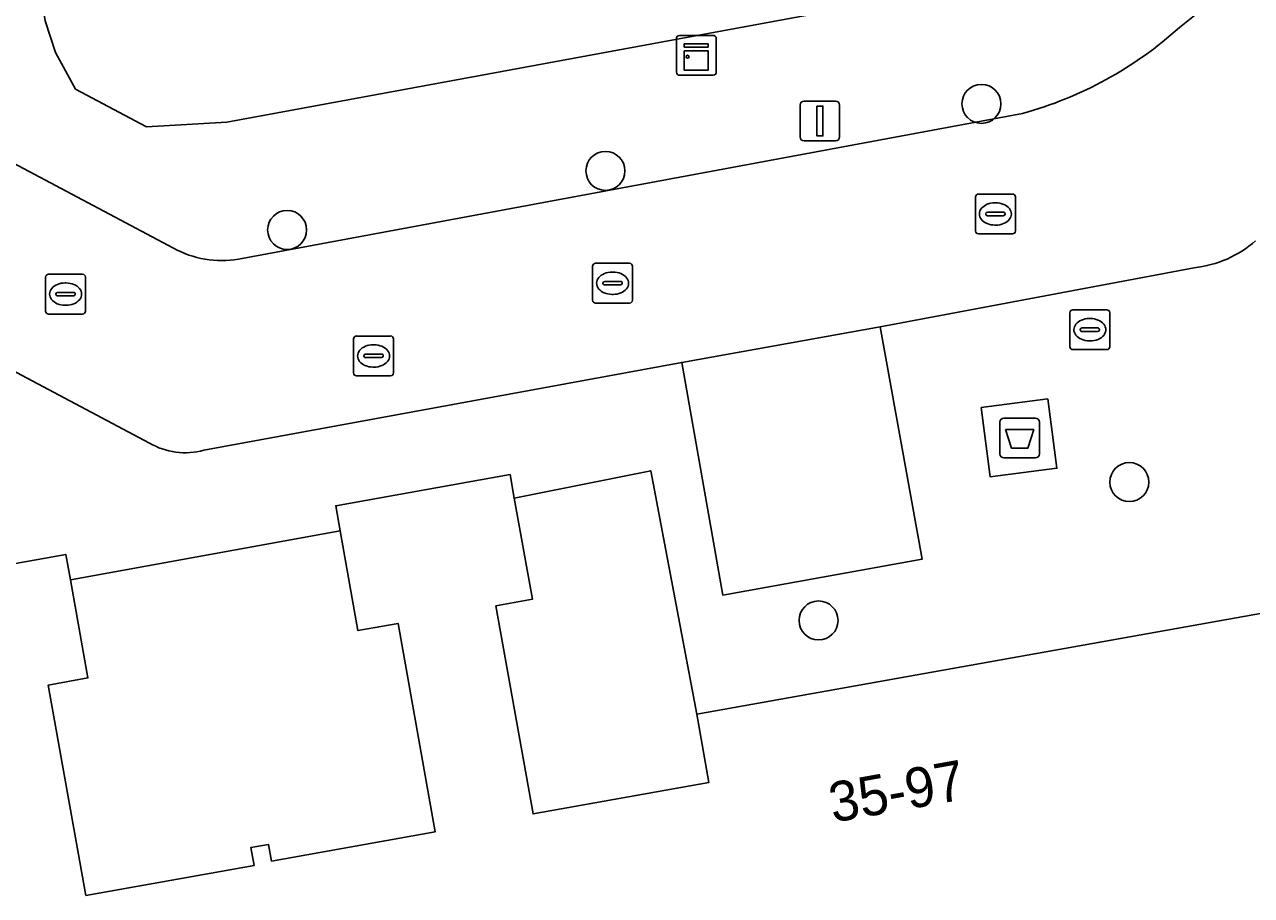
# Model space of a CAD drawing. Extents: x 157793 to 159380, y 380877 to 382313.
# Drawn here: x 158435.44 to 158466.23, y 381426.16 to 381448 of the extents above; entities that cross this region are included whole.
import ezdxf

# ---------------------------------------------------------------- set-up
doc = ezdxf.new("R2010")
doc.units = 0
for name, color, linetype in [('IMGEO_Afval_apart_plaats', 7, 'Continuous'), ('IMGEO_Boom', 7, 'Continuous'), ('IMGEO_Brandkraan', 7, 'Continuous'), ('IMGEO_Erf', 7, 'Continuous'), ('IMGEO_Kast', 7, 'Continuous'), ('IMGEO_Kolk', 7, 'Continuous'), ('IMGEO_Lichtmast', 7, 'Continuous'), ('IMGEO_Pand', 7, 'Continuous'), ('IMGEO_Pand_nummerreeks', 7, 'Continuous'), ('IMGEO_Parkeervlak_open', 7, 'Continuous'), ('IMGEO_Rijbaan_lokaal_open', 7, 'Continuous'), ('IMGEO_Rioolput', 7, 'Continuous'), ('IMGEO_Voetpad_gesloten', 7, 'Continuous'), ('IMGEO_Voetpad_open', 7, 'Continuous')]:
    doc.layers.add(name, color=color, linetype=linetype)

msp = doc.modelspace()

# ---------------------------------------------------------------- linework, layer by layer
at = {"layer": 'IMGEO_Afval_apart_plaats'}
for p, q in [((158459.916, 381437.227), (158459.916, 381438.027)), ((158459.916, 381438.027), (158459.916, 381437.227)), ((158460.016, 381438.127), (158460.806, 381438.127)), ((158460.806, 381438.127), (158460.016, 381438.127)), ((158460.906, 381438.027), (158460.906, 381437.227)), ((158460.906, 381437.227), (158460.906, 381438.027)), ((158460.806, 381437.127), (158460.016, 381437.127)), ((158460.016, 381437.127), (158460.806, 381437.127))]:
    msp.add_line(p, q, dxfattribs=at)
msp.add_lwpolyline([(158460.059, 381437.841), (158460.763, 381437.841), (158460.614, 381437.371), (158460.208, 381437.371), (158460.059, 381437.841)], dxfattribs=at)
for centre, start, end in [((158460.016, 381438.027), 90, 180), ((158460.016, 381438.027), 90, 180), ((158460.806, 381438.027), 0, 90), ((158460.806, 381438.027), 360, 90), ((158460.016, 381437.227), 180, 270), ((158460.016, 381437.227), 180, 270), ((158460.806, 381437.227), 270, 0), ((158460.806, 381437.227), 270, 0)]:
    msp.add_arc(centre, 0.1, start, end, dxfattribs=at)
at = {"layer": 'IMGEO_Boom'}
for centre in [(158459.452, 381446.008), (158450.018, 381444.327), (158442.032, 381442.847), (158463.162, 381436.522), (158455.365, 381433.052)]:
    msp.add_circle(centre, 0.489, dxfattribs=at)
at = {"layer": 'IMGEO_Brandkraan'}
for p, q in [((158461.746, 381440.844), (158462.598, 381440.844)), ((158461.671, 381439.918), (158461.671, 381440.77)), ((158462.159, 381440.624), (158462.184, 381440.624)), ((158462.672, 381440.77), (158462.672, 381439.918)), ((158461.93, 381440.338), (158461.93, 381440.35)), ((158462.368, 381440.301), (158461.97, 381440.301)), ((158461.973, 381440.387), (158462.371, 381440.387)), ((158462.414, 381440.35), (158462.414, 381440.338)), ((158462.182, 381440.064), (158462.157, 381440.064)), ((158462.598, 381439.844), (158461.746, 381439.844))]:
    msp.add_line(p, q, dxfattribs=at)
for points in [[(158461.746, 381440.844), (158462.598, 381440.844)], [(158461.671, 381439.918), (158461.671, 381440.77)], [(158462.672, 381440.77), (158462.672, 381439.918)], [(158462.598, 381439.844), (158461.746, 381439.844)]]:
    msp.add_lwpolyline(points, dxfattribs=at)
for centre, radius, start, end in [((158461.748, 381440.768), 0.0765, 91.552, 178.448), ((158461.748, 381440.768), 0.0765, 91.552, 178.448), ((158462.596, 381440.768), 0.0765, 1.552, 88.448), ((158462.596, 381440.768), 0.0765, 1.552, 88.448), ((158461.97, 381440.347), 0.0403, 85.8775, 175.7526), ((158461.967, 381440.337), 0.0366, 178.938, 274.7102), ((158462.371, 381440.344), 0.043, 264.8664, 352.4533), ((158462.375, 381440.349), 0.0386, 1.7309, 96.639), ((158461.748, 381439.92), 0.0765, 181.552, 268.448), ((158461.748, 381439.92), 0.0765, 181.552, 268.448), ((158462.596, 381439.92), 0.0765, 271.552, 358.448), ((158462.596, 381439.92), 0.0765, 271.552, 358.448)]:
    msp.add_arc(centre, radius, start, end, dxfattribs=at)
for centre, major_axis, ratio, start_param, end_param in [((158462.158, 381440.344), (-0.387, 0.002), 0.722429, 4.712389, 7.853982), ((158462.183, 381440.344), (-0.39, 0.002), 0.717154, 1.570796, 4.712389)]:
    msp.add_ellipse(centre, major_axis=major_axis, ratio=ratio, start_param=start_param, end_param=end_param, dxfattribs=at)
at = {"layer": 'IMGEO_Erf'}
msp.add_lwpolyline([(158435.964, 381448.094), (158436.22, 381447.293), (158436.724, 381446.379), (158438.502, 381445.428), (158440.515, 381445.553), (158459.22, 381448.998)], dxfattribs=at)
for points in [[(158451.154, 381436.805), (158447.73, 381436.121), (158448.184, 381433.582), (158447.27, 381433.418), (158448.203, 381428.2), (158452.616, 381428.989), (158452.31, 381430.699)], [(158436.593, 381434.067), (158437.032, 381431.609), (158436.04, 381431.431), (158436.983, 381426.155), (158441.204, 381426.91), (158441.124, 381427.358), (158441.564, 381427.437), (158441.639, 381427.019), (158445.75, 381427.754), (158444.816, 381432.978), (158443.809, 381432.798), (158443.362, 381435.3)]]:
    msp.add_lwpolyline(points, close=True, dxfattribs=at)
at = {"layer": 'IMGEO_Kast'}
for p, q in [((158451.8, 381446.801), (158451.8, 381447.642)), ((158451.8, 381447.642), (158451.8, 381446.801)), ((158451.875, 381447.726), (158452.716, 381447.726)), ((158452.716, 381447.726), (158451.875, 381447.726)), ((158452.8, 381447.651), (158452.8, 381446.81)), ((158452.8, 381446.81), (158452.8, 381447.651)), ((158452.725, 381446.726), (158451.884, 381446.726)), ((158451.884, 381446.726), (158452.725, 381446.726))]:
    msp.add_line(p, q, dxfattribs=at)
for points in [[(158451.995, 381447.516), (158452.595, 381447.516), (158452.595, 381447.431), (158451.995, 381447.431), (158451.995, 381447.516)], [(158451.995, 381447.341), (158452.595, 381447.341), (158452.595, 381446.852), (158451.995, 381446.852), (158451.995, 381447.341)]]:
    msp.add_lwpolyline(points, dxfattribs=at)
msp.add_circle((158452.079, 381447.19), 0.0377, dxfattribs=at)
for centre, start, end in [((158451.878, 381447.648), 92.4484, 184.2845), ((158451.878, 381447.648), 92.4484, 184.2845), ((158452.722, 381447.648), 2.4484, 94.2845), ((158452.722, 381447.648), 2.4484, 94.2845), ((158451.878, 381446.804), 182.4484, 274.2845), ((158451.878, 381446.804), 182.4484, 274.2845), ((158452.722, 381446.804), 272.4484, 4.2845), ((158452.722, 381446.804), 272.4484, 4.2845)]:
    msp.add_arc(centre, 0.0779, start, end, dxfattribs=at)
at = {"layer": 'IMGEO_Kolk'}
for p, q in [((158459.302, 381442.821), (158459.302, 381443.673)), ((158459.377, 381443.747), (158460.229, 381443.747)), ((158460.303, 381443.673), (158460.303, 381442.821)), ((158459.561, 381443.241), (158459.561, 381443.253)), ((158459.604, 381443.29), (158460.002, 381443.29)), ((158459.79, 381443.527), (158459.815, 381443.527)), ((158460.045, 381443.253), (158460.045, 381443.241)), ((158459.999, 381443.204), (158459.601, 381443.204)), ((158459.813, 381442.967), (158459.788, 381442.967)), ((158460.229, 381442.747), (158459.377, 381442.747)), ((158449.772, 381442.009), (158450.624, 381442.009)), ((158436.047, 381441.737), (158436.899, 381441.737)), ((158449.697, 381441.083), (158449.697, 381441.935)), ((158450.185, 381441.789), (158450.21, 381441.789)), ((158450.698, 381441.935), (158450.698, 381441.083)), ((158435.972, 381440.811), (158435.972, 381441.663)), ((158436.46, 381441.517), (158436.485, 381441.517)), ((158436.973, 381441.663), (158436.973, 381440.811)), ((158449.956, 381441.503), (158449.956, 381441.515)), ((158450.394, 381441.466), (158449.996, 381441.466)), ((158449.999, 381441.552), (158450.397, 381441.552)), ((158450.44, 381441.515), (158450.44, 381441.503)), ((158436.231, 381441.231), (158436.231, 381441.243)), ((158436.669, 381441.194), (158436.271, 381441.194)), ((158436.274, 381441.28), (158436.672, 381441.28)), ((158436.715, 381441.243), (158436.715, 381441.231)), ((158450.208, 381441.229), (158450.183, 381441.229)), ((158436.483, 381440.957), (158436.458, 381440.957)), ((158450.624, 381441.009), (158449.772, 381441.009)), ((158436.899, 381440.737), (158436.047, 381440.737))]:
    msp.add_line(p, q, dxfattribs=at)
for points in [[(158459.302, 381442.821), (158459.302, 381443.673)], [(158459.377, 381443.747), (158460.229, 381443.747)], [(158460.303, 381443.673), (158460.303, 381442.821)], [(158460.229, 381442.747), (158459.377, 381442.747)], [(158449.772, 381442.009), (158450.624, 381442.009)], [(158436.047, 381441.737), (158436.899, 381441.737)], [(158449.697, 381441.083), (158449.697, 381441.935)], [(158450.698, 381441.935), (158450.698, 381441.083)], [(158435.972, 381440.811), (158435.972, 381441.663)], [(158436.973, 381441.663), (158436.973, 381440.811)], [(158450.624, 381441.009), (158449.772, 381441.009)], [(158436.899, 381440.737), (158436.047, 381440.737)]]:
    msp.add_lwpolyline(points, dxfattribs=at)
for centre, radius, start, end in [((158459.379, 381443.671), 0.0765, 91.552, 178.448), ((158459.379, 381443.671), 0.0765, 91.552, 178.448), ((158460.227, 381443.671), 0.0765, 1.552, 88.448), ((158460.227, 381443.671), 0.0765, 1.552, 88.448), ((158459.601, 381443.25), 0.0403, 85.8775, 175.7526), ((158459.598, 381443.24), 0.0366, 178.938, 274.7102), ((158460.002, 381443.247), 0.043, 264.8664, 352.4533), ((158460.006, 381443.252), 0.0386, 1.7309, 96.639), ((158459.379, 381442.823), 0.0765, 181.552, 268.448), ((158459.379, 381442.823), 0.0765, 181.552, 268.448), ((158460.227, 381442.823), 0.0765, 271.552, 358.448), ((158460.227, 381442.823), 0.0765, 271.552, 358.448), ((158449.774, 381441.933), 0.0765, 91.552, 178.448), ((158449.774, 381441.933), 0.0765, 91.552, 178.448), ((158450.622, 381441.933), 0.0765, 1.552, 88.448), ((158450.622, 381441.933), 0.0765, 1.552, 88.448), ((158436.049, 381441.661), 0.0765, 91.552, 178.448), ((158436.049, 381441.661), 0.0765, 91.552, 178.448), ((158436.897, 381441.661), 0.0765, 1.552, 88.448), ((158436.897, 381441.661), 0.0765, 1.552, 88.448), ((158449.996, 381441.512), 0.0403, 85.8775, 175.7526), ((158449.993, 381441.502), 0.0366, 178.938, 274.7102), ((158450.397, 381441.509), 0.043, 264.8664, 352.4533), ((158450.401, 381441.514), 0.0386, 1.7309, 96.639), ((158436.271, 381441.24), 0.0403, 85.8775, 175.7526), ((158436.268, 381441.23), 0.0366, 178.938, 274.7102), ((158436.672, 381441.237), 0.043, 264.8664, 352.4533), ((158436.676, 381441.242), 0.0386, 1.7309, 96.639), ((158449.774, 381441.085), 0.0765, 181.552, 268.448), ((158449.774, 381441.085), 0.0765, 181.552, 268.448), ((158450.622, 381441.085), 0.0765, 271.552, 358.448), ((158450.622, 381441.085), 0.0765, 271.552, 358.448), ((158436.049, 381440.813), 0.0765, 181.552, 268.448), ((158436.049, 381440.813), 0.0765, 181.552, 268.448), ((158436.897, 381440.813), 0.0765, 271.552, 358.448), ((158436.897, 381440.813), 0.0765, 271.552, 358.448)]:
    msp.add_arc(centre, radius, start, end, dxfattribs=at)
for centre, major_axis, ratio, start_param, end_param in [((158459.789, 381443.247), (-0.387, 0.002), 0.722429, 4.712389, 7.853982), ((158459.814, 381443.247), (-0.39, 0.002), 0.717154, 1.570796, 4.712389), ((158450.184, 381441.509), (-0.387, 0.002), 0.722429, 4.712389, 7.853982), ((158450.209, 381441.509), (-0.39, 0.002), 0.717154, 1.570796, 4.712389), ((158436.459, 381441.237), (-0.387, 0.002), 0.722429, 4.712389, 7.853982), ((158436.484, 381441.237), (-0.39, 0.002), 0.717154, 1.570796, 4.712389)]:
    msp.add_ellipse(centre, major_axis=major_axis, ratio=ratio, start_param=start_param, end_param=end_param, dxfattribs=at)
at = {"layer": 'IMGEO_Lichtmast'}
for p, q in [((158455.003, 381446.079), (158455.793, 381446.079)), ((158455.793, 381446.079), (158455.003, 381446.079)), ((158454.903, 381445.179), (158454.903, 381445.979)), ((158454.903, 381445.979), (158454.903, 381445.179)), ((158455.893, 381445.979), (158455.893, 381445.179)), ((158455.893, 381445.179), (158455.893, 381445.979)), ((158455.793, 381445.079), (158455.003, 381445.079)), ((158455.003, 381445.079), (158455.793, 381445.079))]:
    msp.add_line(p, q, dxfattribs=at)
msp.add_lwpolyline([(158455.323, 381445.954), (158455.473, 381445.954), (158455.473, 381445.204), (158455.323, 381445.204), (158455.323, 381445.954)], dxfattribs=at)
for centre, start, end in [((158455.003, 381445.979), 90, 180), ((158455.003, 381445.979), 90, 180), ((158455.793, 381445.979), 0, 90), ((158455.793, 381445.979), 360, 90), ((158455.003, 381445.179), 180, 270), ((158455.003, 381445.179), 180, 270), ((158455.793, 381445.179), 270, 0), ((158455.793, 381445.179), 270, 0)]:
    msp.add_arc(centre, 0.1, start, end, dxfattribs=at)
at = {"layer": 'IMGEO_Pand'}
msp.add_lwpolyline([(158468.885, 381433.662), (158452.31, 381430.699), (158452.616, 381428.989), (158448.203, 381428.2), (158447.27, 381433.418), (158448.184, 381433.582), (158447.73, 381436.121), (158447.625, 381436.709), (158443.25, 381435.927), (158443.362, 381435.3), (158443.809, 381432.798), (158444.816, 381432.978), (158445.75, 381427.754), (158441.639, 381427.019), (158441.564, 381427.437), (158441.124, 381427.358), (158441.204, 381426.91), (158436.983, 381426.155), (158436.04, 381431.431), (158437.032, 381431.609), (158436.593, 381434.067), (158436.479, 381434.707), (158432.026, 381433.911)], dxfattribs=at)
at = {"layer": 'IMGEO_Parkeervlak_open'}
msp.add_lwpolyline([(158456.909, 381440.416), (158451.933, 381439.524), (158452.966, 381433.69), (158457.962, 381434.589)], close=True, dxfattribs=at)
at = {"layer": 'IMGEO_Rijbaan_lokaal_open'}
for points in [[(158470.614, 381452.773), (158470.083, 381452.219), (158464.88, 381448.294), (158464.422, 381447.924)], [(158439.182, 381442.39), (158431.932, 381446.231)], [(158460.486, 381445.766), (158440.809, 381442.117)], [(158439.943, 381437.319), (158451.933, 381439.524), (158456.909, 381440.416), (158464.79, 381441.9)], [(158431.233, 381441.393), (158438.575, 381437.502)]]:
    msp.add_lwpolyline(points, dxfattribs=at)
for centre, radius, start, end in [((158457.86, 381455.225), 9.816, 285.518, 311.9515), ((158440.382, 381444.555), 2.476, 241.0118, 279.938), ((158464.503, 381444.657), 2.772, 275.9406, 311.2792), ((158439.479, 381439.056), 1.798, 239.8146, 284.9467)]:
    msp.add_arc(centre, radius, start, end, dxfattribs=at)
at = {"layer": 'IMGEO_Rioolput'}
for p, q in [((158443.775, 381440.186), (158444.627, 381440.186)), ((158443.7, 381439.26), (158443.7, 381440.112)), ((158444.188, 381439.966), (158444.213, 381439.966)), ((158444.701, 381440.112), (158444.701, 381439.26)), ((158443.959, 381439.68), (158443.959, 381439.692)), ((158444.397, 381439.643), (158443.999, 381439.643)), ((158444.002, 381439.729), (158444.4, 381439.729)), ((158444.443, 381439.692), (158444.443, 381439.68)), ((158444.211, 381439.406), (158444.186, 381439.406)), ((158444.627, 381439.186), (158443.775, 381439.186))]:
    msp.add_line(p, q, dxfattribs=at)
for points in [[(158443.775, 381440.186), (158444.627, 381440.186)], [(158443.7, 381439.26), (158443.7, 381440.112)], [(158444.701, 381440.112), (158444.701, 381439.26)], [(158444.627, 381439.186), (158443.775, 381439.186)]]:
    msp.add_lwpolyline(points, dxfattribs=at)
for centre, radius, start, end in [((158443.777, 381440.11), 0.0765, 91.552, 178.448), ((158443.777, 381440.11), 0.0765, 91.552, 178.448), ((158444.625, 381440.11), 0.0765, 1.552, 88.448), ((158444.625, 381440.11), 0.0765, 1.552, 88.448), ((158443.999, 381439.689), 0.0403, 85.8775, 175.7526), ((158443.996, 381439.679), 0.0366, 178.938, 274.7102), ((158444.4, 381439.686), 0.043, 264.8664, 352.4533), ((158444.404, 381439.691), 0.0386, 1.7309, 96.639), ((158443.777, 381439.262), 0.0765, 181.552, 268.448), ((158443.777, 381439.262), 0.0765, 181.552, 268.448), ((158444.625, 381439.262), 0.0765, 271.552, 358.448), ((158444.625, 381439.262), 0.0765, 271.552, 358.448)]:
    msp.add_arc(centre, radius, start, end, dxfattribs=at)
for centre, major_axis, ratio, start_param, end_param in [((158444.187, 381439.686), (-0.387, 0.002), 0.722429, 4.712389, 7.853982), ((158444.212, 381439.686), (-0.39, 0.002), 0.717154, 1.570796, 4.712389)]:
    msp.add_ellipse(centre, major_axis=major_axis, ratio=ratio, start_param=start_param, end_param=end_param, dxfattribs=at)
at = {"layer": 'IMGEO_Voetpad_gesloten'}
msp.add_lwpolyline([(158461.122, 381438.609), (158459.448, 381438.392), (158459.673, 381436.654), (158461.347, 381436.871)], close=True, dxfattribs=at)
at = {"layer": 'IMGEO_Voetpad_open'}
for points in [[(158464.422, 381447.924), (158464.88, 381448.294), (158464.449, 381450.402), (158461.278, 381449.879), (158461.076, 381449.936), (158459.22, 381448.998), (158440.515, 381445.553), (158438.502, 381445.428), (158436.724, 381446.379), (158436.22, 381447.293), (158435.964, 381448.094), (158435.679, 381449.847), (158435.516, 381450.845), (158434.145, 381450.6), (158394.586, 381443.534), (158389.628, 381442.752), (158388.705, 381442.588), (158389.687, 381438.882), (158390.797, 381439.449), (158430.056, 381446.433)], [(158447.625, 381436.709), (158447.73, 381436.121), (158451.154, 381436.805), (158452.31, 381430.699), (158468.885, 381433.662), (158467.784, 381439.832), (158470.919, 381440.372), (158470.582, 381442.257), (158470.236, 381444.193), (158474.969, 381447.988), (158477.002, 381448.725), (158476.935, 381449.066), (158476.856, 381449.357)], [(158431.932, 381446.231), (158439.182, 381442.39)], [(158440.809, 381442.117), (158460.486, 381445.766)], [(158464.79, 381441.9), (158456.909, 381440.416), (158457.962, 381434.589), (158452.966, 381433.69), (158451.933, 381439.524), (158439.943, 381437.319)], [(158429.544, 381441.688), (158402.292, 381436.775), (158403.177, 381432.417), (158391.741, 381430.36), (158391.883, 381428.934), (158401.691, 381430.632), (158401.802, 381430.651), (158405.232, 381431.245), (158404.617, 381434.627), (158408.23, 381435.291), (158408.121, 381435.824), (158423.88, 381438.688), (158424.032, 381438.042), (158427.357, 381438.657), (158428.488, 381432.615), (158432.139, 381433.276), (158432.026, 381433.911), (158436.479, 381434.707), (158436.593, 381434.067), (158443.362, 381435.3), (158443.25, 381435.927), (158447.625, 381436.709)], [(158438.575, 381437.502), (158431.233, 381441.393)]]:
    msp.add_lwpolyline(points, dxfattribs=at)
msp.add_lwpolyline([(158461.122, 381438.609), (158461.347, 381436.871), (158459.673, 381436.654), (158459.448, 381438.392)], close=True, dxfattribs=at)
for centre, radius, start, end in [((158457.86, 381455.225), 9.816, 285.518, 311.9515), ((158440.382, 381444.555), 2.476, 241.0118, 279.938), ((158464.503, 381444.657), 2.772, 275.9406, 311.2792), ((158439.479, 381439.056), 1.798, 239.8146, 284.9467)]:
    msp.add_arc(centre, radius, start, end, dxfattribs=at)

# ---------------------------------------------------------------- texts
at = {"layer": 'IMGEO_Pand_nummerreeks'}
msp.add_text('35-97', height=1, rotation=10.1356, dxfattribs=at).set_placement((158455.726, 381427.978))

doc.saveas('drawing.dxf')
